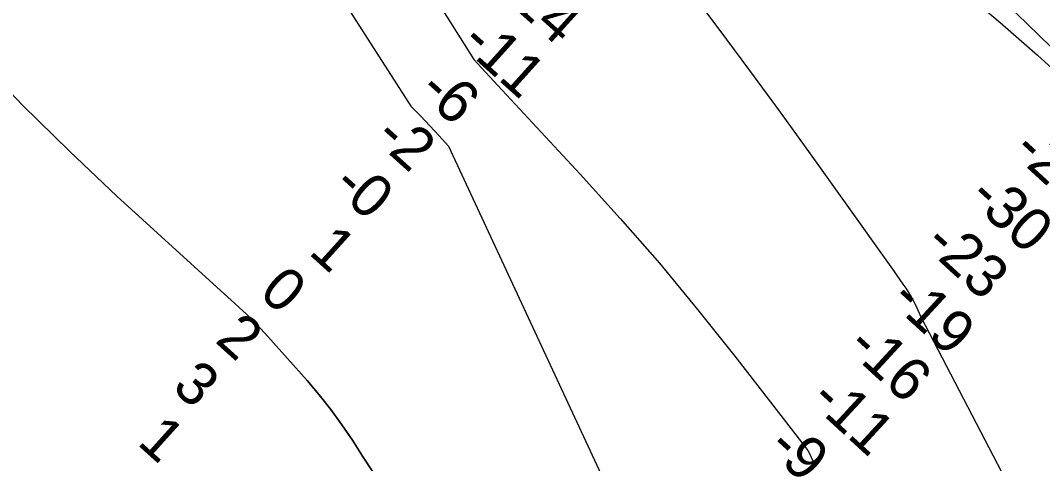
# Model space of a CAD drawing. Extents: x 3192986 to 3230865, y 867483 to 892886.
# Drawn here: x 3216078 to 3217672, y 876501 to 877193 of the extents above; entities that cross this region are included whole.
import ezdxf

# ---------------------------------------------------------------- set-up
doc = ezdxf.new("R2010")
doc.units = 0
for name, color, linetype in [('V-RIVR-RANG', 7, 'Continuous'), ('V-TOPO-DPTH', 7, 'Continuous'), ('V-TOPO-MINR', 7, 'Continuous')]:
    doc.layers.add(name, color=color, linetype=linetype)

msp = doc.modelspace()

# ---------------------------------------------------------------- linework, layer by layer
at = {"layer": 'V-TOPO-DPTH'}
for points in [[(3215686.4, 878153.3), (3216246.1, 877948), (3216259.5, 877938.1), (3216272.5, 877928), (3216285.2, 877917.3), (3216297.5, 877906.2), (3216785.2, 877131.6), (3216797.7, 877118.1), (3216810.2, 877104.6), (3216822.7, 877091.1), (3216950.9, 876952.9), (3217013.4, 876883.7), (3217074.7, 876813.5), (3217134, 876741.6), (3217192.2, 876668.7), (3217300.1, 876529.6), (3217303.2, 876525.4), (3217306.1, 876521), (3217308.6, 876516.4), (3217310.9, 876511.8), (3217315, 876502.8), (3217315.6, 876501.5), (3217317.2, 876497.4)], [(3215686.4, 878153.3), (3216246.1, 877948), (3216259.5, 877938.1), (3216272.5, 877928), (3216285.2, 877917.3), (3216297.5, 877906.2), (3216785.2, 877131.6), (3216797.7, 877118.1), (3216810.2, 877104.6), (3216822.7, 877091.1), (3216950.9, 876952.9), (3217013.4, 876883.7), (3217074.7, 876813.5), (3217134, 876741.6), (3217192.2, 876668.7), (3217300.1, 876529.6), (3217303.2, 876525.4), (3217306.1, 876521), (3217308.6, 876516.4), (3217310.9, 876511.8), (3217315, 876502.8), (3217315.6, 876501.5), (3217317.2, 876497.4)], [(3216627.3, 876487.8), (3216611.4, 876512.5), (3216595.6, 876537.2), (3216579.2, 876561.4), (3216562.1, 876585.1), (3216543.9, 876608), (3216525, 876630.4), (3216463.9, 876699.3), (3216453, 876711.1), (3216441.9, 876722.7), (3216430.5, 876734), (3216418.7, 876745), (3216228.3, 876918.5), (3216154.2, 876988.4), (3216081.7, 877059.8), (3216011.6, 877133.5), (3215943, 877208.9), (3215808.4, 877361.9), (3215148, 877824.2)], [(3216627.3, 876487.8), (3216611.4, 876512.5), (3216595.6, 876537.2), (3216579.2, 876561.4), (3216562.1, 876585.1), (3216543.9, 876608), (3216525, 876630.4), (3216463.9, 876699.3), (3216453, 876711.1), (3216441.9, 876722.7), (3216430.5, 876734), (3216418.7, 876745), (3216228.3, 876918.5), (3216154.2, 876988.4), (3216081.7, 877059.8), (3216011.6, 877133.5), (3215943, 877208.9), (3215808.4, 877361.9), (3215148, 877824.2)], [(3217771.9, 877067.3), (3217299.6, 877527)], [(3217771.9, 877067.3), (3217299.6, 877527)], [(3217229.3, 877507.7), (3217606.1, 877189.4), (3217635.3, 877164.3), (3217664.3, 877138.8), (3217692.8, 877112.8)], [(3217229.3, 877507.7), (3217606.1, 877189.4), (3217635.3, 877164.3), (3217664.3, 877138.8), (3217692.8, 877112.8)], [(3217921.3, 875886.3), (3217482.7, 876729.2), (3217478.1, 876740), (3217475, 876746.9), (3217471.5, 876754.1), (3217467.8, 876761.1), (3217463.7, 876767.9), (3217459.4, 876774.6), (3217454.9, 876781.2), (3217450.3, 876787.8), (3217445.7, 876794.3), (3217441.1, 876800.9), (3217357.2, 876919.1), (3217310.4, 876984.5), (3217263.3, 877049.8), (3217215.7, 877114.6), (3217167.7, 877179.3), (3217040.1, 877350)], [(3217921.3, 875886.3), (3217482.7, 876729.2), (3217478.1, 876740), (3217475, 876746.9), (3217471.5, 876754.1), (3217467.8, 876761.1), (3217463.7, 876767.9), (3217459.4, 876774.6), (3217454.9, 876781.2), (3217450.3, 876787.8), (3217445.7, 876794.3), (3217441.1, 876800.9), (3217357.2, 876919.1), (3217310.4, 876984.5), (3217263.3, 877049.8), (3217215.7, 877114.6), (3217167.7, 877179.3), (3217040.1, 877350)]]:
    msp.add_lwpolyline(points, dxfattribs=at)
at = {"layer": 'V-TOPO-MINR'}
for points in [[(3213621.7, 878506.8), (3214497.7, 878346.3), (3214508.1, 878341.6), (3215362.2, 878095.1), (3215376.5, 878094.8), (3215415.1, 878093), (3215428.1, 878091.7), (3215440.8, 878089.4), (3215453.2, 878085.6), (3216154.6, 877852.7), (3216158, 877852.8), (3216161.3, 877852), (3216184.4, 877843), (3216686.9, 877059), (3216701.9, 877043.7), (3216716.7, 877028.2), (3216731.2, 877012.4), (3216745.5, 876996.4), (3217087, 876261.1)], [(3215686.4, 878153.3), (3216246.1, 877948), (3216259.5, 877938.1), (3216272.5, 877928), (3216285.2, 877917.3), (3216297.5, 877906.2), (3216785.2, 877131.6), (3216797.7, 877118.1), (3216810.2, 877104.6), (3216822.7, 877091.1), (3216950.9, 876952.9), (3217013.4, 876883.7), (3217074.7, 876813.5), (3217134, 876741.6), (3217192.2, 876668.7), (3217300.1, 876529.6), (3217303.2, 876525.4), (3217306.1, 876521), (3217308.6, 876516.4), (3217310.9, 876511.8), (3217315, 876502.8), (3217315.6, 876501.5), (3217317.2, 876497.4)], [(3215148, 877824.2), (3215808.4, 877361.9), (3215943, 877208.9), (3216011.6, 877133.5), (3216081.7, 877059.8), (3216154.2, 876988.4), (3216228.3, 876918.5), (3216418.7, 876745), (3216430.5, 876734), (3216441.9, 876722.7), (3216453, 876711.1), (3216463.9, 876699.3), (3216525, 876630.4), (3216543.9, 876608), (3216562.1, 876585.1), (3216579.2, 876561.4), (3216595.6, 876537.2), (3216611.4, 876512.5), (3216627.3, 876487.8)], [(3217771.9, 877067.3), (3217299.6, 877527)], [(3217229.3, 877507.7), (3217606.1, 877189.4), (3217635.3, 877164.3), (3217664.3, 877138.8), (3217692.8, 877112.8)], [(3217921.3, 875886.3), (3217482.7, 876729.2), (3217478.1, 876740), (3217475, 876746.9), (3217471.5, 876754.1), (3217467.8, 876761.1), (3217463.7, 876767.9), (3217459.4, 876774.6), (3217454.9, 876781.2), (3217450.3, 876787.8), (3217445.7, 876794.3), (3217441.1, 876800.9), (3217357.2, 876919.1), (3217310.4, 876984.5), (3217263.3, 877049.8), (3217215.7, 877114.6), (3217167.7, 877179.3), (3217040.1, 877350)]]:
    msp.add_lwpolyline(points, dxfattribs=at)

# ---------------------------------------------------------------- texts
at = {"layer": 'V-RIVR-RANG'}
for s, rotation, p in [('-14', 318.0233, (3216818.9, 877238)), ('-11', 318.0233, (3216762.2, 877154.4)), ('-6', 318.0233, (3216696.3, 877079.2)), ('-2', 318.0233, (3216627.5, 877006.6)), ('-29', 317.4292, (3217622.9, 876985.8)), ('-0', 318.0233, (3216562, 876931.1)), ('-30', 317.4292, (3217554.1, 876913.2)), ('1', 318.0233, (3216525.7, 876829.2)), ('-23', 317.4292, (3217485, 876840.8)), ('0', 318.0233, (3216447.8, 876764.7)), ('-19', 317.4292, (3217432.4, 876753.4)), ('2', 318.0233, (3216379.6, 876691.6)), ('-16', 317.4292, (3217364.5, 876679.9)), ('3', 318.0233, (3216312.3, 876617.6)), ('-11', 317.4292, (3217307.2, 876596.8)), ('1', 318.0233, (3216258.2, 876531.8)), ('-9', 317.4292, (3217240.7, 876522.1))]:
    msp.add_text(s, height=67, rotation=rotation, dxfattribs=at).set_placement(p)

doc.saveas('drawing.dxf')
